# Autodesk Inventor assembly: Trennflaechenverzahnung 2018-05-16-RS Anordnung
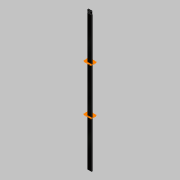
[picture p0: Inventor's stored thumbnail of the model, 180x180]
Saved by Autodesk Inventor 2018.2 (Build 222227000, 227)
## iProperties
Created: 2018-05
Part Number: Trennflaechenverzahnung 2018-05-16-RS Anordnung
Material: Generisch
Document SubType Name: Assembly
Designer: Roland
Author: Roland
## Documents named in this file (3)
- Q:\Betrieb\Programme\Inventor\Beispiele\Geometrie\Trennflächenverzahnung\Trennflaechenverzahnung 2018-05-16-RS Anordnung.iam
- Q:\Betrieb\Programme\Inventor\Beispiele\Geometrie\Trennflächenverzahnung\Trennflaechenverzahnung 2018-05-16-RS Ausgangsvolumen.ipt
- Q:\Betrieb\Programme\Inventor\Beispiele\Geometrie\Trennflächenverzahnung\Trennflaechenverzahnung 2018-05-16-RS Struktur.ipt
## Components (3 placed, 2 different names)
1. RE-ENG-043744komplett:1
2. Trennflächenverzahnung 2018-05-16:1
3. Trennflächenverzahnung 2018-05-16:2
